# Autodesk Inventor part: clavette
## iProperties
Author: robert
Shininess: 20.0
Angle Display Precision: 2
Document Length Units: 11269
Document Angle Units: 11283
Document Time Units: 11279
Document Mass Units: 11290
Document Length Units Precision: 3
Document Angle Units Precision: 2
Compacted: True
PropertySet Name: _Private Model Information
Created: 2002-06
Part Number: clavette
Material: Par défaut
Document SubType Name: Modélisation
Designer: robert
Control State: 0
Master: False
Checked Out: False
PropertySet Name: Design Tracking Control
Density: 0.0
Volumn: 0.0
Area: 0.0
PropertySet Name: Model Information
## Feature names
1. Extrusion1
